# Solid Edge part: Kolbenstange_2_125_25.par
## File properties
Username: ahadarics
Dokumentum tartalom típus: 0
Author: ahadarics
Last saved by: ahadarics
Revision: 78
Sűrűség: 0,000 kg/m^3
Pontosság: 0,990
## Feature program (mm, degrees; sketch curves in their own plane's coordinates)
base feature "unnamed BaseFeature 1"
thread "unnamed Thread 1"
chamfer "Letörés_1"  SetBackValue2 = 25 deg
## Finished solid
Body 1: solid body, 19 faces, 31 edges, 16 vertices.
  Faces by surface: plane 8, cylinder 5, cone 3, torus 3
  Edges by curve: circle 18, line 8, curve on surface 3, ellipse 2
Bounding box of the edges (mm; curved faces can reach further): 125.000 x 125.000 x 192.000, from (-62.5, -62.5, -96) to (62.5, 62.5, 96).
Cylindrical faces by radius (mm): R11.9 x1, R13.5 x1, R15.5 x1, R16 x1, R62.5 x1
Conical faces (half-angle, radius in mm at the cone's reference point): 25 deg R11.9006 x1, 30 deg R15.75 x1, 60 deg R12.7 x1
Toroidal faces (ring radius, tube radius in mm): R12.7 r0.8 x2, R13.3 r2.2 x1
Planar faces by outward normal: +x 1, +z 3, -x 1, -z 1, oblique 2
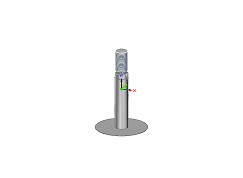
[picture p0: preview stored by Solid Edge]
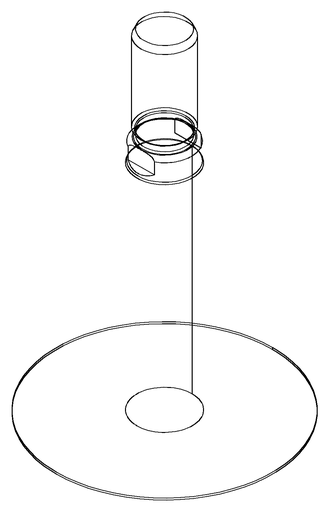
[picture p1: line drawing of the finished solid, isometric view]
